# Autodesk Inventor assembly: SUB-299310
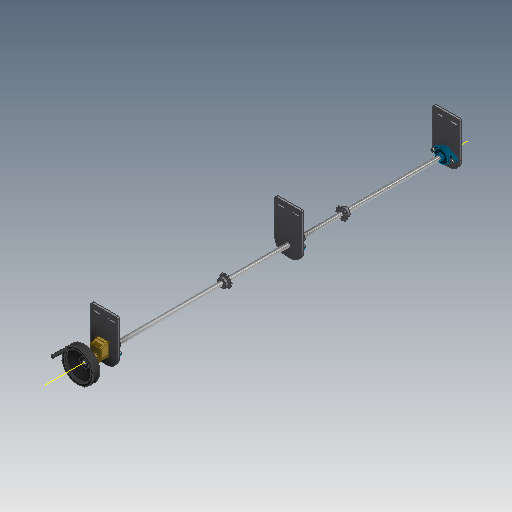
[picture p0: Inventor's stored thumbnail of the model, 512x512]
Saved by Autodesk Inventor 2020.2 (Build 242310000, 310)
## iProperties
Created: 2000-02
Part Number: SUB-299310
Document SubType Name: Assembly
Designer: sspink
Mass: 13100.5 g
Surface Area: 4565.02 cm^2
Volume: 2119.53 cm^3
Density: 6.18088 g/cm^3
Control State: 0
Checked Out: False
Master: False
Shininess: 0.0
Length Units: 11269
Angle Units: 11279
Time Units: 11290
Mass Units: 11283
Length Display Precision: 3
Angle Display Precision: 2
Compacted: True
Dimensions: 273,4x1813,5x215,6 mm
Mass: 13,101 kg
DocNumber: SUB-299310.iam
Folder: 01 - Themengebiete\Simplification\01 - Packaging machine\
VDS_Category: 3D Komponenten
Density: 0.0
Volumn: 0.0
Area: 0.0
PropertySet Name: Model Information
Author: sspink
Revision Number: -
Title: SUB-299310
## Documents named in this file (15)
- D:\07 - DEMODATEN\OTX 2019 - Dataset - UPDATE - Dez2019\Designs\07-Packing machine\SUB-299310.iam
- D:\07 - DEMODATEN\OTX 2019 - Dataset - UPDATE - Dez2019\Designs\07-Packing machine\Parts\ADSK-011309.ipt
- D:\07 - DEMODATEN\OTX 2019 - Dataset - UPDATE - Dez2019\Designs\07-Packing machine\Parts\ADSK-011667.ipt
- D:\07 - DEMODATEN\OTX 2019 - Dataset - UPDATE - Dez2019\Designs\07-Packing machine\Parts\ADSK-011768.ipt
- D:\07 - DEMODATEN\OTX 2019 - Dataset - UPDATE - Dez2019\Designs\07-Packing machine\Parts\ADSK-011665.ipt
- D:\07 - DEMODATEN\OTX 2019 - Dataset - UPDATE - Dez2019\Designs\07-Packing machine\Parts\ADSK-011714.ipt
- D:\07 - DEMODATEN\OTX 2019 - Dataset - UPDATE - Dez2019\Designs\07-Packing machine\Parts\ADSK-011666.ipt
- D:\07 - DEMODATEN\OTX 2019 - Dataset - UPDATE - Dez2019\Designs\07-Packing machine\Parts\ADSK-011716.ipt
- D:\07 - DEMODATEN\OTX 2019 - Dataset - UPDATE - Dez2019\Designs\07-Packing machine\Parts\ADSK-011723.ipt
- D:\07 - DEMODATEN\OTX 2019 - Dataset - UPDATE - Dez2019\Content Center Files\de-DE\ISO 2491 - A\ISO 2491 - A  5 x 3 x 16.ipt
- D:\07 - DEMODATEN\OTX 2019 - Dataset - UPDATE - Dez2019\Content Center Files\de-DE\ISO 4026\ISO 4026 - M5 x 6 - ISO.ipt
- D:\07 - DEMODATEN\OTX 2019 - Dataset - UPDATE - Dez2019\Content Center Files\de-DE\ISO 2491 - A\ISO 2491 - A  5 x 3 x 28.ipt
- D:\07 - DEMODATEN\OTX 2019 - Dataset - UPDATE - Dez2019\Content Center Files\de-DE\ISO 4026\ISO 4026 - M5 x 8 - ISO.ipt
- D:\07 - DEMODATEN\OTX 2019 - Dataset - UPDATE - Dez2019\Content Center Files\de-DE\DIN 125-1  B\DIN 125-1 - B 8,4.ipt
- D:\07 - DEMODATEN\OTX 2019 - Dataset - UPDATE - Dez2019\Content Center Files\de-DE\ISO 4762(2)\ISO 4762 - M8 x 20ISO.ipt
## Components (32 placed, 14 different names)
1. ADSK-011667:1 — Passend:17, Fluchtend:1, Passend:19, Passend:20, Fluchtend:2, Passend:21, Fluchtend:3, Passend:22, Tangential:1, Passend:27, Passend:29, Passend:32, Passend:33, Passend:34, Passend:35, Passend:36, Tangential:2, Passend:41, Fluchtend:6, Passend:42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
2. ADSK-011665:1 — Insert:2, Insert:3, Mate:7, Passend:14, Passend:15, Passend:16, Fluchtend:1, Passend:24, Passend:26, Fluchtend:4, Passend:31
3. ADSK-011666:1 — Insert:5, Fluchtend:4, Passend:30, Fluchtend:5
4. ADSK-011714:1 — Insert:2, Insert:3, Passend:49
5. ADSK-011714:2 — Insert:5, Passend:29, Passend:30
6. ADSK-011716:1 — Passend:47, Passend:49
7. ADSK-011716:2 — Passend:48, Passend:50
8. ADSK-011309:1 — Passend:21, Fluchtend:3, Passend:22, Passend:23, Passend:37
9. ADSK-011768:1 — Passend:14, Passend:15, Passend:16, Passend:17
10. ADSK-011665:2 — Insert:7, Insert:8, Passend:26, Passend:28
11. ADSK-011714:3 — Insert:7, Insert:8, Passend:27, Passend:50
12. ADSK-011723:1 — Passend:40, Passend:41, Fluchtend:6, Passend:45
13. ADSK-011723:2 — Passend:31, Passend:32, Passend:33, Passend:38, Passend:40
14. DIN 125-1 B B 8,4:1 — Passend:60, Passend:62
15. DIN 125-1 B B 8,4:2
16. DIN 125-1 B B 8,4:3 — Passend:56, Passend:58
17. DIN 125-1 B B 8,4:4
18. DIN 125-1 B B 8,4:5 — Passend:52, Passend:54
19. DIN 125-1 B B 8,4:6
20. ISO 4762 M8 x 20:1 — Passend:52
21. ISO 4762 M8 x 20:2 — Passend:54
22. ISO 4762 M8 x 20:3 — Passend:56
23. ISO 4762 M8 x 20:4 — Passend:58
24. ISO 4762 M8 x 20:5 — Passend:60
25. ISO 4762 M8 x 20:6 — Passend:62
26. ISO 2491 A A  5 x 3 x 16:1 — Passend:19, Passend:20, Fluchtend:2
27. ISO 4026 M5 x 6:1 — Passend:23, Tangential:1
28. ISO 2491 A A  5 x 3 x 28:1 — Passend:34, Passend:35, Passend:36, Passend:39
29. ISO 4026 M5 x 6:2 — Passend:37, Tangential:2
30. ISO 4026 M5 x 8:1 — Passend:38, Passend:39
31. ISO 2491 A A  5 x 3 x 28:2 — Passend:42, Passend:43, Passend:44, Passend:46
32. ISO 4026 M5 x 8:2 — Passend:45, Passend:46
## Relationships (57: Mate 43, Flush 7, Insert 5, Tangent 2)
- Insert:2: ADSK-011665:1 ↔ ADSK-011714:1
- Insert:3: ADSK-011665:1 ↔ ADSK-011714:1
- Insert:5: ADSK-011666:1 ↔ ADSK-011714:2
- Insert:7: ADSK-011665:2 ↔ ADSK-011714:3
- Insert:8: ADSK-011665:2 ↔ ADSK-011714:3
- Mate:7: ADSK-011665:1
- Passend:14 [Mate]: ADSK-011665:1 ↔ ADSK-011768:1
- Passend:15 [Mate]: ADSK-011665:1 ↔ ADSK-011768:1
- Passend:16 [Mate]: ADSK-011665:1 ↔ ADSK-011768:1
- Passend:17 [Mate]: ADSK-011667:1 ↔ ADSK-011768:1
- Fluchtend:1 [Flush]: ADSK-011667:1 ↔ ADSK-011665:1
- Passend:19 [Mate]: ADSK-011667:1 ↔ ISO 2491 A A  5 x 3 x 16:1
- Passend:20 [Mate]: ADSK-011667:1 ↔ ISO 2491 A A  5 x 3 x 16:1
- Fluchtend:2 [Flush]: ADSK-011667:1 ↔ ISO 2491 A A  5 x 3 x 16:1
- Passend:21 [Mate]: ADSK-011667:1 ↔ ADSK-011309:1
- Fluchtend:3 [Flush]: ADSK-011667:1 ↔ ADSK-011309:1
- Passend:22 [Mate]: ADSK-011667:1 ↔ ADSK-011309:1
- Passend:23 [Mate]: ADSK-011309:1 ↔ ISO 4026 M5 x 6:1
- Tangential:1: ADSK-011667:1 ↔ ISO 4026 M5 x 6:1
- Passend:24 [Mate]: ADSK-011665:1
- Passend:26 [Mate]: ADSK-011665:1 ↔ ADSK-011665:2
- Passend:27 [Mate]: ADSK-011667:1 ↔ ADSK-011714:3
- Passend:28 [Mate]: ADSK-011665:2
- Fluchtend:4 [Flush]: ADSK-011665:1 ↔ ADSK-011666:1
- Passend:29 [Mate]: ADSK-011667:1 ↔ ADSK-011714:2
- Passend:30 [Mate]: ADSK-011666:1 ↔ ADSK-011714:2
- Fluchtend:5 [Flush]: ADSK-011666:1
- Passend:31 [Mate]: ADSK-011665:1 ↔ ADSK-011723:2
- Passend:32 [Mate]: ADSK-011667:1 ↔ ADSK-011723:2
- Passend:33 [Mate]: ADSK-011667:1 ↔ ADSK-011723:2
- Passend:34 [Mate]: ADSK-011667:1 ↔ ISO 2491 A A  5 x 3 x 28:1
- Passend:35 [Mate]: ADSK-011667:1 ↔ ISO 2491 A A  5 x 3 x 28:1
- Passend:36 [Mate]: ADSK-011667:1 ↔ ISO 2491 A A  5 x 3 x 28:1
- Passend:37 [Mate]: ADSK-011309:1 ↔ ISO 4026 M5 x 6:2
- Tangential:2: ADSK-011667:1 ↔ ISO 4026 M5 x 6:2
- Passend:38 [Mate]: ADSK-011723:2 ↔ ISO 4026 M5 x 8:1
- Passend:39 [Mate]: ISO 2491 A A  5 x 3 x 28:1 ↔ ISO 4026 M5 x 8:1
- Passend:40 [Mate]: ADSK-011723:1 ↔ ADSK-011723:2
- Passend:41 [Mate]: ADSK-011667:1 ↔ ADSK-011723:1
- Fluchtend:6 [Flush]: ADSK-011667:1 ↔ ADSK-011723:1
- Passend:42 [Mate]: ADSK-011667:1 ↔ ISO 2491 A A  5 x 3 x 28:2
- Passend:43 [Mate]: ADSK-011667:1 ↔ ISO 2491 A A  5 x 3 x 28:2
- Passend:44 [Mate]: ADSK-011667:1 ↔ ISO 2491 A A  5 x 3 x 28:2
- Passend:45 [Mate]: ADSK-011723:1 ↔ ISO 4026 M5 x 8:2
- Passend:46 [Mate]: ISO 2491 A A  5 x 3 x 28:2 ↔ ISO 4026 M5 x 8:2
- Passend:47 [Mate]: ADSK-011667:1 ↔ ADSK-011716:1
- Passend:48 [Mate]: ADSK-011667:1 ↔ ADSK-011716:2
- Passend:49 [Mate]: ADSK-011714:1 ↔ ADSK-011716:1
- Passend:50 [Mate]: ADSK-011716:2 ↔ ADSK-011714:3
- Passend:52 [Mate]: DIN 125-1 B B 8,4:5 ↔ ISO 4762 M8 x 20:1
- Passend:54 [Mate]: DIN 125-1 B B 8,4:5 ↔ ISO 4762 M8 x 20:2
- Passend:56 [Mate]: DIN 125-1 B B 8,4:3 ↔ ISO 4762 M8 x 20:3
- Passend:58 [Mate]: DIN 125-1 B B 8,4:3 ↔ ISO 4762 M8 x 20:4
- Passend:60 [Mate]: DIN 125-1 B B 8,4:1 ↔ ISO 4762 M8 x 20:5
- Passend:62 [Mate]: DIN 125-1 B B 8,4:1 ↔ ISO 4762 M8 x 20:6
- Fluchtend:7 [Flush]: ADSK-011667:1
- Passend:65 [Mate]: ADSK-011667:1
